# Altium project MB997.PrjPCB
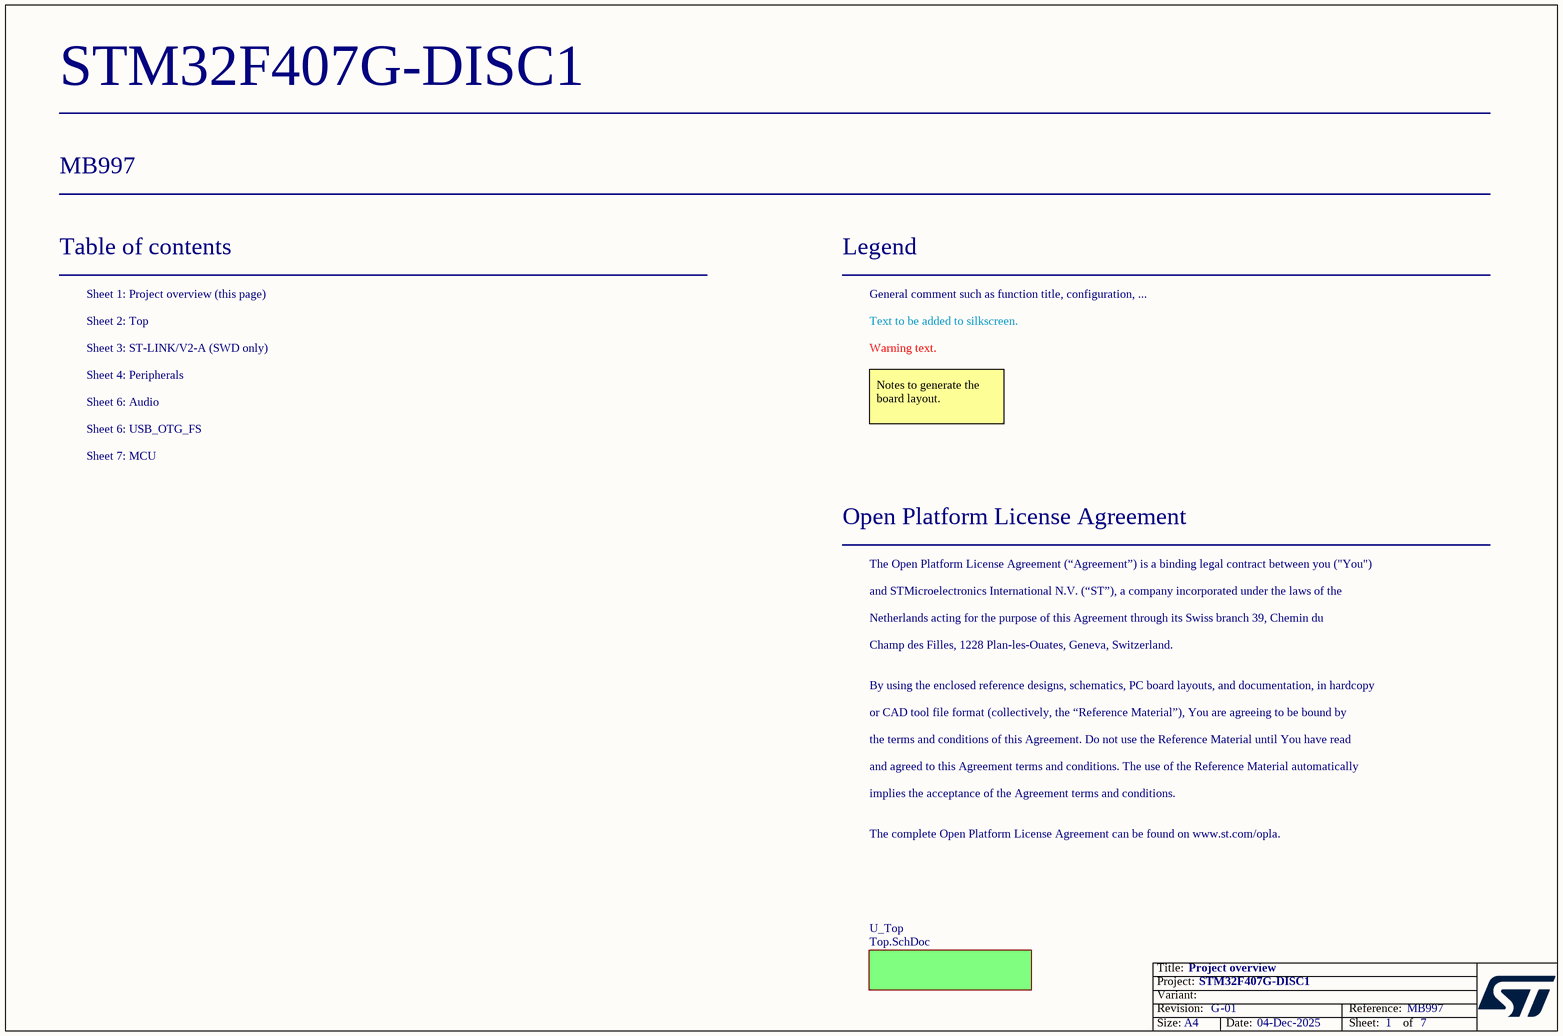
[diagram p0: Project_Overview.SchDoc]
Board_reference: MB997; Board_PCB_REVISION: G; Board_name: STM32F407G-DISC1; Board_Document_Date: 04-Dec-2025; Board_assembly_revision: 01
7 sheets, 207 parts. Net scope: flat (ports and power ports of the same name join across sheets).
Board file: MB997.PcbDoc
Sheets:
  Project_Overview.SchDoc
    U_Top = Top.SchDoc
      U_ST_LINK = ST_LINK_V2.SCHDOC
      U_STM32Fx = STM32Fx.SchDoc
      U_USB_OTG_FS = USB_OTG_FS.SchDoc
      U_Audio = Audio.SchDoc
      U_IO_Peripherals = IO_Peripherals.SchDoc

## Sheet Project_Overview.SchDoc: Project overview
size A4; Date: Not used; ApprovedBy: Not used; CheckedBy: Not used; Author: Not used; CompanyName: STMicroelectronics; DrawnBy: Not used; Engineer: Not used; Organization: Not used; Address1: Not used; Address2: Not used; Address3: Not used; Address4: Not used; DocumentNumber: 1; Revision: Not used; SheetNumber: 1; SheetTotal: 7

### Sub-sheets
U_Top = Top.SchDoc: no entries

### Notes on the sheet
- Table of contents
- Sheet 1: Project overview (this page)
- Legend
- General comment such as function title, configuration, ...
- Sheet 2: Top
- Sheet 3: ST-LINK/V2-A (SWD only)
- Sheet 4: Peripherals
- Text to be added to silkscreen.
- Warning text.
- Sheet 6: Audio
- Sheet 6: USB_OTG_FS
- Notes to generate the board layout.
- Sheet 7: MCU
- Open Platform License Agreement
- The Open Platform License Agreement (“Agreement”) is a binding legal contract between you ("You")
- and STMicroelectronics International N.V. (“ST”), a company incorporated under the laws of the
- Netherlands acting for the purpose of this Agreement through its Swiss branch 39, Chemin du
- Champ des Filles, 1228 Plan-les-Ouates, Geneva, Switzerland.
- By using the enclosed reference designs, schematics, PC board layouts, and documentation, in hardcopy
- or CAD tool file format (collectively, the “Reference Material”), You are agreeing to be bound by
- the terms and conditions of this Agreement. Do not use the Reference Material until You have read
- and agreed to this Agreement terms and conditions. The use of the Reference Material automatically
- implies the acceptance of the Agreement terms and conditions.
- The complete Open Platform License Agreement can be found on www.st.com/opla.

## Sheet Top.SchDoc: TOP
size A4; DocumentNumber: 2; Revision: D.1(PCB.SCH); SheetNumber: 2; SheetTotal: 7
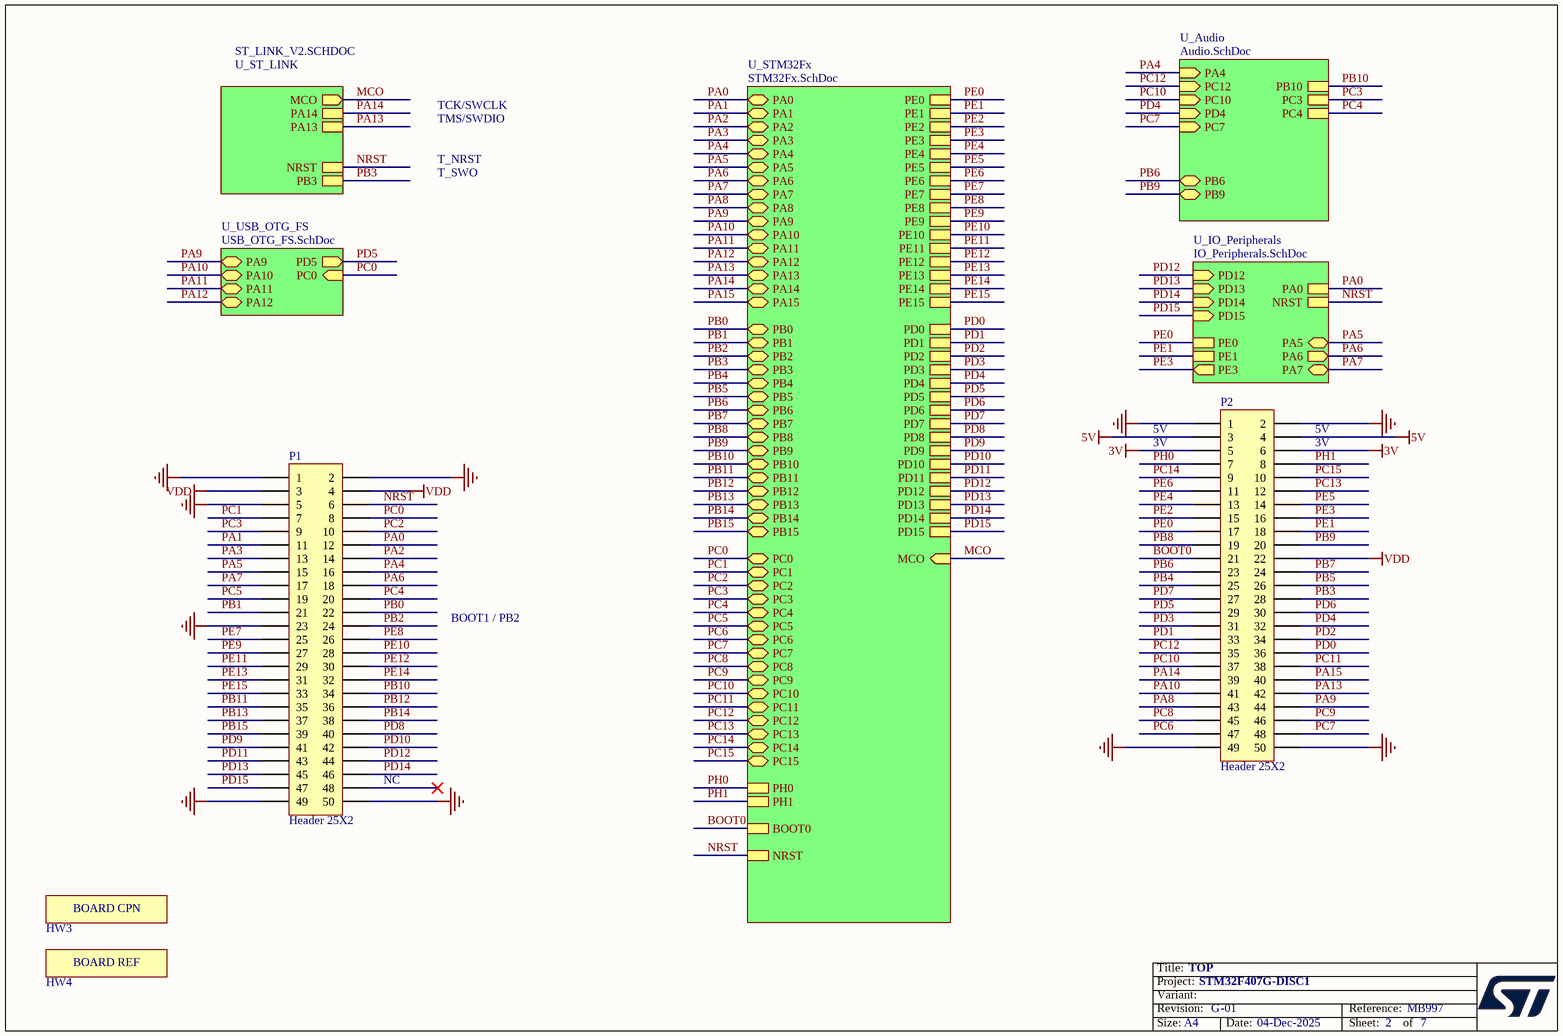
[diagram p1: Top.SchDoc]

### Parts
HW3  STICKER_BOARD_CPN  [STICKER_25X9_]  (value not drawn)  (no BOM)
HW4  STICKER_BOARD_REF  [STICKER_25X9_]  (value not drawn)  (no BOM)
P1  Header 25X2  [HEAD25X2$2F$2.54]
P2  Header 25X2  [HEAD25X2$2F$2.54]

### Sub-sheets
U_Audio = Audio.SchDoc: PA4 (in), PC12 (in), PC10 (in), PB6 (bidir), PB9 (bidir), PD4 (in), PC7 (in), PC3, PB10, PC4
U_IO_Peripherals = IO_Peripherals.SchDoc: PD12 (in), PA0, NRST, PD13 (in), PD14 (in), PD15 (in), PE3 (out), PA6 (out), PA7 (bidir), PA5 (bidir), PE0, PE1
U_ST_LINK = ST_LINK_V2.SCHDOC: PA13, PA14, NRST, PB3, MCO (out)
U_STM32Fx = STM32Fx.SchDoc: PA13 (bidir), PA14 (bidir), PA15 (bidir), PA12 (bidir), PA0 (bidir), PA1 (bidir), PA2 (bidir), PA3 (bidir), PA4 (bidir), PA5 (bidir), PA6 (bidir), PA7 (bidir), PA8 (bidir), PA9 (bidir), PA10 (bidir), PA11 (bidir), PB12 (bidir), PB0 (bidir), PB1 (bidir), PB2 (bidir), PB3 (bidir), PB4 (bidir), PB5 (bidir), PB6 (bidir), PB7 (bidir), PB8 (bidir), PB9 (bidir), PB10 (bidir), PB11 (bidir), PB13 (bidir), PB14 (bidir), PB15 (bidir), PC3 (bidir), PC15 (bidir), PC14 (bidir), PC13 (bidir), PC12 (bidir), PC11 (bidir), PC10 (bidir), PC9 (bidir), PC8 (bidir), PC7 (bidir), PC6 (bidir), PC5 (bidir), PC4 (bidir), PC2 (bidir), PC1 (bidir), PC0 (bidir), PD2, BOOT0, PH1, PH0, NRST, MCO (in), PE0, PE1, PE2, PE3, PE4, PE5, PE6, PE7, PE8, PE9, PE10, PE11, PE12, PE13, PE14, PE15, PD0, PD1, PD3, PD4, PD5, PD6, PD7, PD8, PD9, PD10, PD11, PD12, PD13, PD14, PD15
U_USB_OTG_FS = USB_OTG_FS.SchDoc: PD5 (out), PA11 (bidir), PA12 (bidir), PC0 (in), PA10 (bidir), PA9 (bidir)

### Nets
3V: P2.5 P2.6
5V: P2.3 P2.4
GND: P1.1 P1.2 P1.5 P1.23 P1.49 P1.50 P2.1 P2.2 P2.49 P2.50
VDD: P1.3 P1.4 P2.22
BOOT0: P2.21 ; sheet U_STM32Fx/BOOT0
MCO: sheet U_ST_LINK/MCO, sheet U_STM32Fx/MCO
NRST: P1.6 ; sheet U_ST_LINK/NRST, sheet U_STM32Fx/NRST, sheet U_IO_Peripherals/NRST
PA0: P1.12 ; sheet U_STM32Fx/PA0, sheet U_IO_Peripherals/PA0
PA1: P1.11 ; sheet U_STM32Fx/PA1
PA2: P1.14 ; sheet U_STM32Fx/PA2
PA3: P1.13 ; sheet U_STM32Fx/PA3
PA4: P1.16 ; sheet U_STM32Fx/PA4, sheet U_Audio/PA4
PA5: P1.15 ; sheet U_STM32Fx/PA5, sheet U_IO_Peripherals/PA5
PA6: P1.18 ; sheet U_STM32Fx/PA6, sheet U_IO_Peripherals/PA6
PA7: P1.17 ; sheet U_STM32Fx/PA7, sheet U_IO_Peripherals/PA7
PA8: P2.43 ; sheet U_STM32Fx/PA8
PA9: P2.44 ; sheet U_STM32Fx/PA9, sheet U_USB_OTG_FS/PA9
PA10: P2.41 ; sheet U_STM32Fx/PA10, sheet U_USB_OTG_FS/PA10
PA11: sheet U_STM32Fx/PA11, sheet U_USB_OTG_FS/PA11
PA12: sheet U_STM32Fx/PA12, sheet U_USB_OTG_FS/PA12
PA13: P2.42 ; sheet U_ST_LINK/PA13, sheet U_STM32Fx/PA13
PA14: P2.39 ; sheet U_ST_LINK/PA14, sheet U_STM32Fx/PA14
PA15: P2.40 ; sheet U_STM32Fx/PA15
PB0: P1.22 ; sheet U_STM32Fx/PB0
PB1: P1.21 ; sheet U_STM32Fx/PB1
PB2: P1.24 ; sheet U_STM32Fx/PB2
PB3: P2.28 ; sheet U_ST_LINK/PB3, sheet U_STM32Fx/PB3
PB4: P2.25 ; sheet U_STM32Fx/PB4
PB5: P2.26 ; sheet U_STM32Fx/PB5
PB6: P2.23 ; sheet U_STM32Fx/PB6, sheet U_Audio/PB6
PB7: P2.24 ; sheet U_STM32Fx/PB7
PB8: P2.19 ; sheet U_STM32Fx/PB8
PB9: P2.20 ; sheet U_STM32Fx/PB9, sheet U_Audio/PB9
PB10: P1.34 ; sheet U_STM32Fx/PB10, sheet U_Audio/PB10
PB11: P1.35 ; sheet U_STM32Fx/PB11
PB12: P1.36 ; sheet U_STM32Fx/PB12
PB13: P1.37 ; sheet U_STM32Fx/PB13
PB14: P1.38 ; sheet U_STM32Fx/PB14
PB15: P1.39 ; sheet U_STM32Fx/PB15
PC0: P1.8 ; sheet U_STM32Fx/PC0, sheet U_USB_OTG_FS/PC0
PC1: P1.7 ; sheet U_STM32Fx/PC1
PC2: P1.10 ; sheet U_STM32Fx/PC2
PC3: P1.9 ; sheet U_STM32Fx/PC3, sheet U_Audio/PC3
PC4: P1.20 ; sheet U_STM32Fx/PC4, sheet U_Audio/PC4
PC5: P1.19 ; sheet U_STM32Fx/PC5
PC6: P2.47 ; sheet U_STM32Fx/PC6
PC7: P2.48 ; sheet U_STM32Fx/PC7, sheet U_Audio/PC7
PC8: P2.45 ; sheet U_STM32Fx/PC8
PC9: P2.46 ; sheet U_STM32Fx/PC9
PC10: P2.37 ; sheet U_STM32Fx/PC10, sheet U_Audio/PC10
PC11: P2.38 ; sheet U_STM32Fx/PC11
PC12: P2.35 ; sheet U_STM32Fx/PC12, sheet U_Audio/PC12
PC13: P2.12 ; sheet U_STM32Fx/PC13
PC14: P2.9 ; sheet U_STM32Fx/PC14
PC15: P2.10 ; sheet U_STM32Fx/PC15
PD0: P2.36 ; sheet U_STM32Fx/PD0
PD1: P2.33 ; sheet U_STM32Fx/PD1
PD2: P2.34 ; sheet U_STM32Fx/PD2
PD3: P2.31 ; sheet U_STM32Fx/PD3
PD4: P2.32 ; sheet U_STM32Fx/PD4, sheet U_Audio/PD4
PD5: P2.29 ; sheet U_STM32Fx/PD5, sheet U_USB_OTG_FS/PD5
PD6: P2.30 ; sheet U_STM32Fx/PD6
PD7: P2.27 ; sheet U_STM32Fx/PD7
PD8: P1.40 ; sheet U_STM32Fx/PD8
PD9: P1.41 ; sheet U_STM32Fx/PD9
PD10: P1.42 ; sheet U_STM32Fx/PD10
PD11: P1.43 ; sheet U_STM32Fx/PD11
PD12: P1.44 ; sheet U_STM32Fx/PD12, sheet U_IO_Peripherals/PD12
PD13: P1.45 ; sheet U_STM32Fx/PD13, sheet U_IO_Peripherals/PD13
PD14: P1.46 ; sheet U_STM32Fx/PD14, sheet U_IO_Peripherals/PD14
PD15: P1.47 ; sheet U_STM32Fx/PD15, sheet U_IO_Peripherals/PD15
PE0: P2.17 ; sheet U_STM32Fx/PE0, sheet U_IO_Peripherals/PE0
PE1: P2.18 ; sheet U_STM32Fx/PE1, sheet U_IO_Peripherals/PE1
PE2: P2.15 ; sheet U_STM32Fx/PE2
PE3: P2.16 ; sheet U_STM32Fx/PE3, sheet U_IO_Peripherals/PE3
PE4: P2.13 ; sheet U_STM32Fx/PE4
PE5: P2.14 ; sheet U_STM32Fx/PE5
PE6: P2.11 ; sheet U_STM32Fx/PE6
PE7: P1.25 ; sheet U_STM32Fx/PE7
PE8: P1.26 ; sheet U_STM32Fx/PE8
PE9: P1.27 ; sheet U_STM32Fx/PE9
PE10: P1.28 ; sheet U_STM32Fx/PE10
PE11: P1.29 ; sheet U_STM32Fx/PE11
PE12: P1.30 ; sheet U_STM32Fx/PE12
PE13: P1.31 ; sheet U_STM32Fx/PE13
PE14: P1.32 ; sheet U_STM32Fx/PE14
PE15: P1.33 ; sheet U_STM32Fx/PE15
PH0: P2.7 ; sheet U_STM32Fx/PH0
PH1: P2.8 ; sheet U_STM32Fx/PH1

Not connected (* = marked no-connect by the designer): P1 48*

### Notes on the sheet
- TCK/SWCLK
- TMS/SWDIO
- T_SWO
- T_NRST
- 5V
- 3V
- (near P2) 5V
- (near P2) 3V
- BOOT1 / PB2
- (near P1) NC

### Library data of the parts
P1 = Header 25X2: Header, 25-Pin, Dual row; Manuf_Part_1: 313250S141145; Manuf_1: LYCN
P2 = Header 25X2: Header, 25-Pin, Dual row; Manuf_1: LYCN; Manuf_Part_1: 313250S141145

## Sheet ST_LINK_V2.SCHDOC: ST-LINK/V2-A (SWD only)
size A4; DocumentNumber: 3; Revision: D.1(PCB.SCH); SheetNumber: 3; SheetTotal: 7
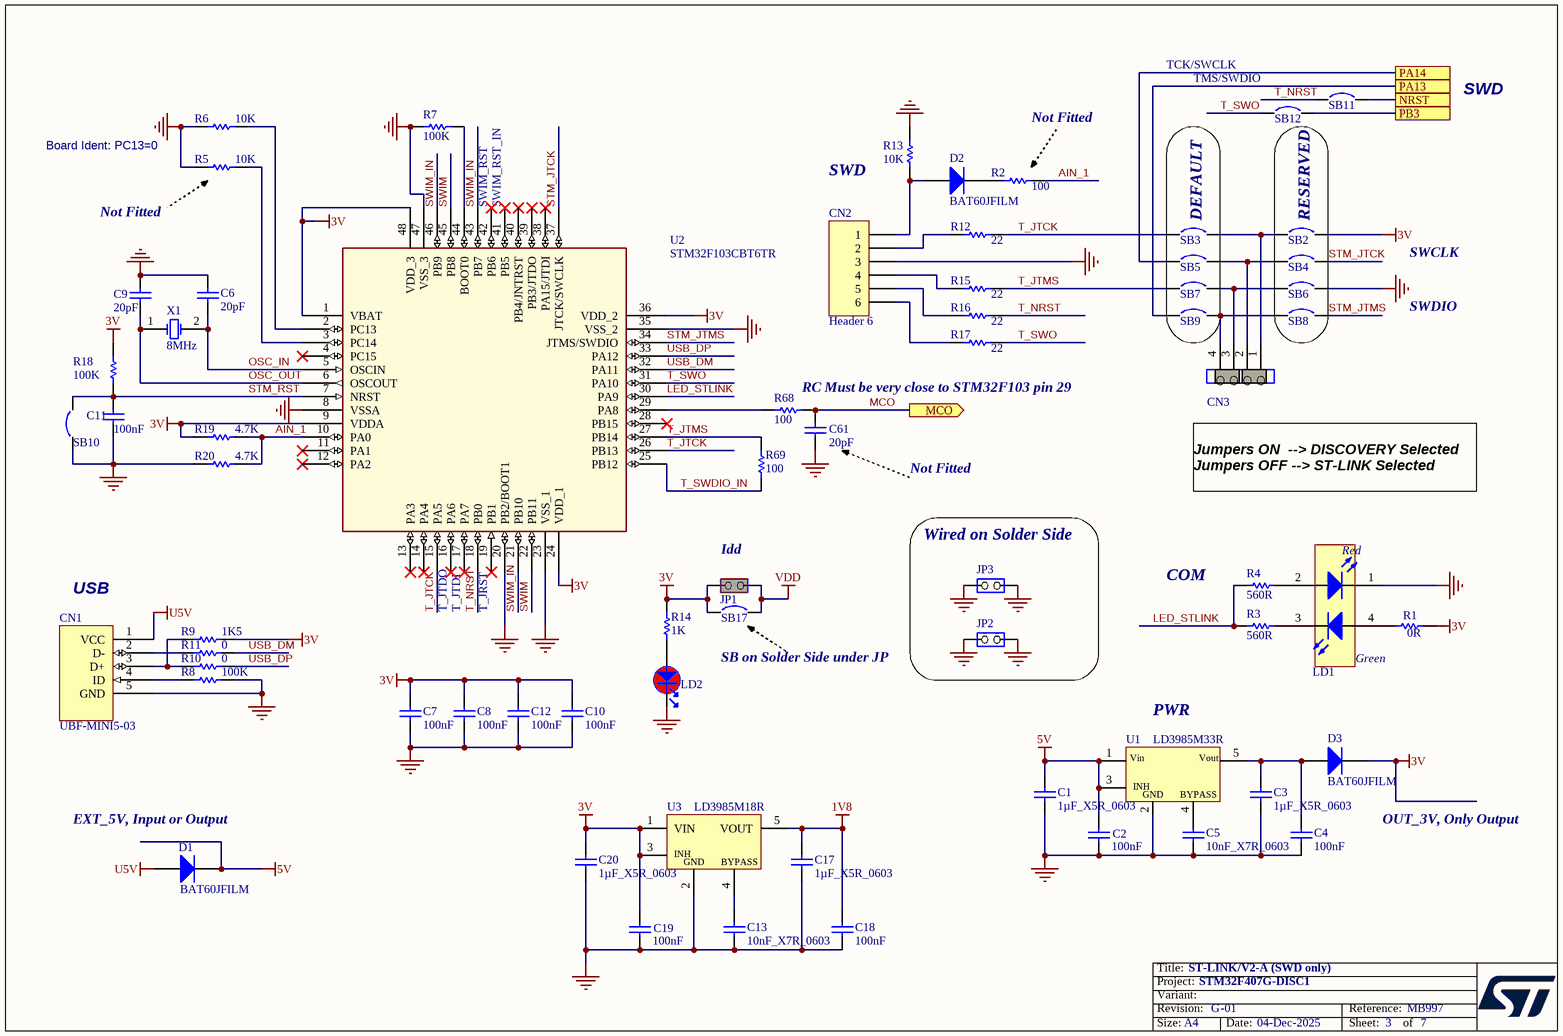
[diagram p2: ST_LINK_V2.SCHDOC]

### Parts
C1  1µF_X5R_0603  [0603C]
C2  100nF  [0402C]
C3  1µF_X5R_0603  [0603C]
C4  100nF  [0402C]
C5  10nF_X7R_0603  [0603C]
C6  20pF  [0402C]
C7  100nF  [0402C]
C8  100nF  [0402C]
C9  20pF  [0402C]
C10  100nF  [0402C]
C11  100nF  [0402C]
C12  100nF  [0402C]
C13  10nF_X7R_0603  [0603C]
C17  1µF_X5R_0603  [0603C]
C18  100nF  [0402C]
C19  100nF  [0402C]
C20  1µF_X5R_0603  [0603C]
C61  20pF  [0603C]
CN1  UBF-MINI5-03  [USB-MINI-B-SMD-A_]
CN2  Header 6  [HEADER6$2F$2.54]
CN3  Jumper_Header 4x1 fitted 1-2_3-4  [CON_SAMTEC_TSW-104-07-G-S]  (value not drawn)
D1  BAT60JFILM  [SOD323$2F$A]
D2  BAT60JFILM  [SOD323$2F$A]
D3  BAT60JFILM  [SOD323$2F$A]
JP1  Jumper_Header 2x1 Fitted  [CON_SAMTEC_TSW-102-07-G-S]  (value not drawn)
JP2  (no value)  [SIP2$2F$2.54]
JP3  (no value)  [SIP2$2F$2.54]
LD1  LD_BICOLOR_CMS_1  [LED_BI-GR_HSMF-A201-A00J1]  (value not drawn)
LD2  LED_red  [LED_0603_RED]  (value not drawn)
R1  0R  [0603R]
R2  100  [0402R]
R3  560R  [0402R]
R4  560R  [0402R]
R5  10K  [0402R]
R6  10K  [0402R]
R7  100K  [0402R]
R8  100K  [0402R]
R9  1K5  [0402R]
R10  0  [0603R]
R11  0  [0603R]
R12  22  [0402R]
R13  10K  [0402R]
R14  1K  [0402R]
R15  22  [0402R]
R16  22  [0402R]
R17  22  [0402R]
R18  100K  [0402R]
R19  4.7K  [0402R]
R20  4.7K  [0402R]
R68  100  [0603R]
R69  100  [0402R]
SB2  Circuit Breaker  [JUMPER]  (value not drawn)
SB3  Circuit Breaker  [JUMPER]  (value not drawn)
SB4  Circuit Breaker  [JUMPER]  (value not drawn)
SB5  Circuit Breaker  [JUMPER]  (value not drawn)
SB6  Circuit Breaker  [JUMPER]  (value not drawn)
SB7  Circuit Breaker  [JUMPER]  (value not drawn)
SB8  Circuit Breaker  [JUMPER]  (value not drawn)
SB9  Circuit Breaker  [JUMPER]  (value not drawn)
SB10  Circuit Breaker  [JUMPER]  (value not drawn)
SB11  Circuit Breaker  [JUMPER]  (value not drawn)
SB12  Circuit Breaker  [JUMPER]  (value not drawn)
SB17  Circuit Breaker  [JUMPER]  (value not drawn)
U1  LD3985M33R  [SOT-23-5L]
U2  STM32F103CBT6TR  [LQFP48$2F$0.5MM$5C$9X9B]
U3  LD3985M18R  [REG_SOT23-5L]
X1  8MHz  [HC-49A]

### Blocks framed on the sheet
DEFAULT: SB3 SB5 SB7 SB9
RESERVED: SB2 SB4 SB6 SB8
Wired on Solder Side: JP2 JP3

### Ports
MCO (out), NRST, PA13, PA14, PB3

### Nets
1V8: C17.1 C18.2 U3.5(VOUT)
3V: C7.2 C8.2 C10.2 C12.1 C19.2 C20.2 D3.2(K) JP1.1(COMMON) R1.2 R9.2 R14.2 R18.2 R19.1 SB2.2 SB17.1 U2.1(VBAT) U2.9(VDDA) U2.24(VDD_1) U2.36(VDD_2) U2.48(VDD_3) U3.1(VIN) U3.3(CE)
5V: C1.2 C2.2 D1.2(K) U1.1(Vin) U1.3(CE)
GND: C1.1 C2.1 C3.2 C4.1 C5.1 C6.1 C7.1 C8.1 C9.1 C10.1 C11.1 C12.2 C13.1 C17.2 C18.1 C19.1 C20.1 C61.2 CN1.5(GND) CN2.3 JP2.1(COMMON) JP2.2(NO) JP3.1(COMMON) JP3.2(NO) LD1.1(RED_cathode) LD2.2 R5.1 R6.1 R7.1 R8.2 R13.2 R20.1 SB6.2 SB10.1 U1.2(GND) U2.8(VSSA) U2.20(PB2/BOOT1) U2.23(VSS_1) U2.35(VSS_2) U2.47(VSS_3) U3.2(GND)
U5V: CN1.1(VCC) D1.1(A)
VDD: JP1.2(NO) SB17.2
AIN_1: R2.2 R19.2 R20.2 U2.10(PA0)
LED_STLINK: R3.1 R4.1 U2.30(PA9)
MCO: C61.1 R68.2 ; port MCO
NRST: SB11.2 ; port NRST
OSC_IN: C6.2 U2.5(OSCIN) X1.2(OSC2)
OSC_OUT: C9.2 U2.6(OSCOUT) X1.1(OSC1)
PA13: SB9.1 ; port PA13
PA14: SB5.1 ; port PA14
PB3: SB12.2 ; port PB3
STM_JTCK: SB4.2 U2.37(JTCK/SWCLK)
STM_JTMS: SB8.2 U2.34(JTMS/SWDIO)
STM_RST: C11.2 R18.1 SB10.2 U2.7(NRST)
SWIM: U2.22(PB11) U2.45(PB8)
SWIM_IN: U2.21(PB10) U2.43(PB7) U2.46(PB9)
T_JTCK: R12.2 SB3.1 U2.15(PA5) U2.26(PB13)
T_JTMS: R15.2 R69.2 SB7.1 U2.27(PB14)
T_NRST: R16.2 SB11.1 U2.18(PB0)
T_SWDIO_IN: R69.1 U2.25(PB12)
T_SWO: R17.2 SB12.1 U2.31(PA10)
USB_DM: R11.2 U2.32(PA11)
USB_DP: R10.2 U2.33(PA12)
NetC3_1: C3.1 C4.2 D3.1(A) U1.5(Vout)
NetC5_2: C5.2 U1.4(BYPASS)
NetC13_2: C13.2 U3.4(BYPASS)
NetCN1_2: CN1.2(D-) R11.1
NetCN1_3: CN1.3(D+) R9.1 R10.1
NetCN1_4: CN1.4(ID) R8.1
NetCN2_1: CN2.1 D2.1(A) R13.1
NetCN2_2: CN2.2 R12.1
NetCN2_4: CN2.4 R15.1
NetCN2_5: CN2.5 R16.1
NetCN2_6: CN2.6 R17.1
NetCN3_1: CN3.1 SB2.1 SB3.2
NetCN3_2: CN3.2 SB4.1 SB5.2
NetCN3_3: CN3.3 SB6.1 SB7.2
NetCN3_4: CN3.4 SB8.1 SB9.2
NetD2_2: D2.2(K) R2.1
NetLD1_2: LD1.2(Red_anode) R4.2
NetLD1_3: LD1.3(YellowGreen_cathode) R3.2
NetLD1_4: LD1.4(YellowGreen_anode) R1.1
NetLD2_1: LD2.1 R14.1
NetR5_2: R5.2 U2.3(PC14)
NetR6_2: R6.2 U2.2(PC13)
NetR7_2: R7.2 U2.44(BOOT0)
NetR68_1: R68.1 U2.29(PA8)

Not connected (* = marked no-connect by the designer): U2 4(PC15)* 11(PA1)* 12(PA2)* 13(PA3)* 14(PA4)* 16(PA6)* 17(PA7)* 19(PB1)* 28(PB15)* 38(PA15/JTDI)* 39(PB3/JTDO)* 40(PB4/JNTRST)* 41(PB5)* 42(PB6)*

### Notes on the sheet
- TCK/SWCLK
- (near SB12) TMS/SWDIO
- SWD
- Board Ident: PC13=0
- Not Fitted
- SWIM_RST
- SWIM_RST_IN
- SWCLK
- SWDIO
- (near R68) RC Must be very close to STM32F103 pin 29
- Jumpers ON  --> DISCOVERY Selected
  Jumpers OFF --> ST-LINK Selected
- (near JP1) Idd
- COM
- (near CN1) USB
- (near U2) T_JTDO
- (near U2) T_JTDI
- (near U2) T_JRST
- SB on Solder Side under JP
- (near U1) PWR
- (near D1) EXT_5V, Input or Output
- OUT_3V, Only Output

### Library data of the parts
C1 C3 C17 C20 = CAP SMD 0603  X5R 1µF 25V 10%: 0603  X5R 1µF; Manuf_1: YAGEO; Manuf_Part_1: CC0603KRX5R7BB105; Value: 1uF; Rated voltage: 25V; Tolerance: 10%
C2 C4 C7 C8 C10-C12 C18 C19 = Cap: Capacitor; Manuf_Part_1: CC0402KRX7R7BB104; Manuf_1: YAGEO
C5 C13 = CAP SMD 0603  X7R 10000PF 50V 10%: 0603  X7R 10NF; Manuf_1: YAGEO; Manuf_Part_1: CC0603KRX7R9BB103; Order code RS: 2040779; Rated voltage: 50V; Tolerance: 10%
C6 C9 = Cap: Capacitor; Manuf_Part_1: CC0402JRNPO9BN200; Manuf_1: YAGEO
C61 = Cap: Capacitor; Fitted: NO
CN1 = USB-MINI-typeB connector_: Manuf_1: MTCONN
CN2 = Header 6: Header, 6-Pin; Manuf_Part_1: 313106S141116; Manuf_1: LYCN
D1-D3 = BAT60JFILM: Manuf_1: STM; Code - JEDEC: DO-214-AB; Provided: ST
JP2 JP3 = JP2: Manuf_1: LYCN; Manuf_Part_1: 313102S141145
R1 = res1: Resistor; Manuf_Part_1: RC0603JR-070RL; Manuf_1: YAGEO; Value: 0
R2 = res1: Resistor; Fitted: NO
R3 R4 = res1: Resistor, 560R, 0402, +/-1%, 1/16W; Manuf_Part_1: RC0402FR-07560RL; Manuf_1: YAGEO; Value: 560
R5 = res1: Resistor; Manuf_Part_1: RC0402FR-0710KL; Manuf_1: YAGEO; Fitted: NO
R6 R13 = res1: Resistor; Manuf_Part_1: RC0402FR-0710KL; Manuf_1: YAGEO
R7 R8 R18 = res1: Resistor; Manuf_Part_1: RC0402FR-07100KL; Manuf_1: YAGEO
R9 = res1: Resistor; Manuf_Part_1: RC0402FR-071K5L; Manuf_1: YAGEO
R10 R11 = res1: Resistor; Manuf_Part_1: RC0603JR-070RL; Manuf_1: YAGEO
R12 R15-R17 = res1: Resistor; Manuf_Part_1: RC0402FR-0722RL; Manuf_1: YAGEO
R14 = res1: Resistor; Manuf_Part_1: RC0402FR-071KL; Manuf_1: YAGEO
R19 R20 = res1: Resistor; Manuf_Part_1: RC0402FR-074K7L; Manuf_1: YAGEO
R68 = res1: Resistor; Manuf_Part_1: RC0603FR-07100RL; Manuf_1: YAGEO
R69 = res1: Resistor; Manuf_Part_1: RC0402FR-07100RL; Manuf_1: YAGEO
SB2 SB4 SB6 SB8 SB10 SB17 = Circuit Breaker: Solder: NO
SB3 SB5 SB7 SB9 SB11 SB12 = Circuit Breaker: Solder: YES
U1 = LD3985M33R: Ultra low drop-low noise BiCMOS voltage, regulators low ESR capacitors compatible; Manuf_1: STM; Provided: ST
U2 = STM32F103CBT6: Medium-density performance line ARM-based 32-bit MCU with 128KB Flash; Manuf_1: STM; Ref St: xxxxxxxx; Provided: ST; ECCN_US/EU: 3A991A2/NEC
X1 = XTAL: Crystal Oscillator; Manuf_Part_1: HC-49S-C20QSA-8.000MHZ; Manuf_1: jfvny

## Sheet STM32Fx.SchDoc: MCU
size A4; DocumentNumber: 7; Revision: D.1(PCB.SCH); SheetNumber: 7; SheetTotal: 7
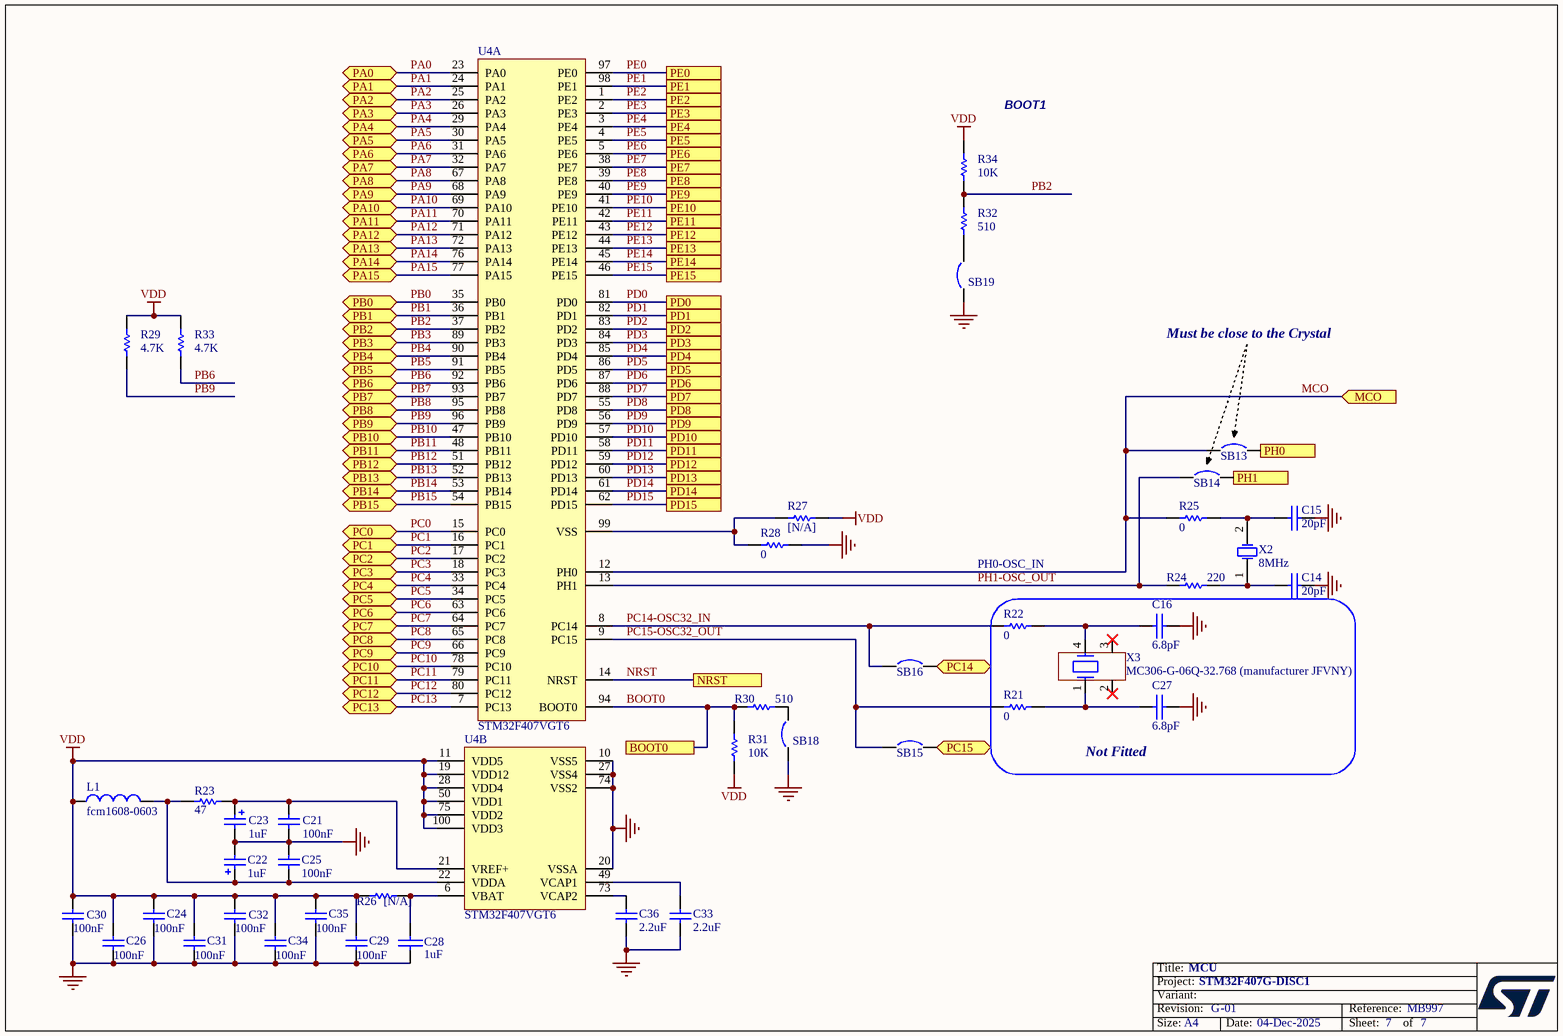
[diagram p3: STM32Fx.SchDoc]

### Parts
C14  20pF  [0603C]
C15  20pF  [0603C]
C16  6.8pF  [0603C]
C21  100nF  [0402C]
C22  1uF  [CASE-A]
C23  1uF  [CASE-A]
C24  100nF  [0402C]
C25  100nF  [0402C]
C26  100nF  [0402C]
C27  6.8pF  [0603C]
C28  1uF  [0603C]
C29  100nF  [0402C]
C30  100nF  [0402C]
C31  100nF  [0402C]
C32  100nF  [0402C]
C33  2.2uF  [CASE-A]
C34  100nF  [0402C]
C35  100nF  [0402C]
C36  2.2uF  [CASE-A]
L1  fcm1608-0603  [0603L]
R21  0  [0603R]
R22  0  [0603R]
R23  47  [0603R]
R24  220  [0603R]
R25  0  [0603R]
R26  [N/A]  [0603R]
R27  [N/A]  [0603R]
R28  0  [0603R]
R29  4.7K  [0402R]
R30  510  [0603R]
R31  10K  [0402R]
R32  510  [0603R]
R33  4.7K  [0402R]
R34  10K  [0402R]
SB13  Circuit Breaker  [JUMPER]  (value not drawn)
SB14  Circuit Breaker  [JUMPER]  (value not drawn)
SB15  Circuit Breaker  [JUMPER]  (value not drawn)
SB16  Circuit Breaker  [JUMPER]  (value not drawn)
SB18  Circuit Breaker  [JUMPER]  (value not drawn)
SB19  Circuit Breaker  [JUMPER]  (value not drawn)
U4  STM32F407VGT6  [QFP100-1414]  (parts A,B of 2)
X2  8MHz  [HC-49A]
X3  MC306-G-06Q-32.768 (manufacturer JFVNY)  [MC306-CRYSTAL]

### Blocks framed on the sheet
Not Fitted: C16 C27 R21 R22 X3

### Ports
BOOT0, MCO (in), NRST, PA0 (bidir), PA1 (bidir), PA2 (bidir), PA3 (bidir), PA4 (bidir), PA5 (bidir), PA6 (bidir), PA7 (bidir), PA8 (bidir), PA9 (bidir), PA10 (bidir), PA11 (bidir), PA12 (bidir), PA13 (bidir), PA14 (bidir), PA15 (bidir), PB0 (bidir), PB1 (bidir), PB2 (bidir), PB3 (bidir), PB4 (bidir), PB5 (bidir), PB6 (bidir), PB7 (bidir), PB8 (bidir), PB9 (bidir), PB10 (bidir), PB11 (bidir), PB12 (bidir), PB13 (bidir), PB14 (bidir), PB15 (bidir), PC0 (bidir), PC1 (bidir), PC2 (bidir), PC3 (bidir), PC4 (bidir), PC5 (bidir), PC6 (bidir), PC7 (bidir), PC8 (bidir), PC9 (bidir), PC10 (bidir), PC11 (bidir), PC12 (bidir), PC13 (bidir), PC14 (bidir), PC15 (bidir), PD0, PD1, PD2, PD3, PD4, PD5, PD6, PD7, PD8, PD9, PD10, PD11, PD12, PD13, PD14, PD15, PE0, PE1, PE2, PE3, PE4, PE5, PE6, PE7, PE8, PE9, PE10, PE11, PE12, PE13, PE14, PE15, PH0, PH1

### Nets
GND: C14.1 C15.1 C16.2 C21.1 C22.2 C23.2 C24.2 C25.1 C26.1 C27.2 C28.2 C29.1 C30.1 C31.1 C32.1 C33.2 C34.1 C35.2 C36.2 R28.2 SB18.1 SB19.1 U4.10(VSS5) U4.20(VSSA) U4.27(VSS4) U4.74(VSS2)
VDD: C24.1 C26.2 C29.2 C30.2 C31.2 C32.2 C34.2 C35.1 L1.1 R26.1 R27.2 R29.1 R31.2 R33.1 R34.1 U4.11(VDD5) U4.19(VDD12) U4.28(VDD4) U4.50(VDD1) U4.75(VDD2) U4.100(VDD3)
BOOT0: R30.2 R31.1 U4.94(BOOT0) ; port BOOT0
MCO: R25.1 SB13.1 U4.12(PH0) ; port MCO
NRST: U4.14(NRST) ; port NRST
PA0: U4.23(PA0) ; port PA0
PA1: U4.24(PA1) ; port PA1
PA2: U4.25(PA2) ; port PA2
PA3: U4.26(PA3) ; port PA3
PA4: U4.29(PA4) ; port PA4
PA5: U4.30(PA5) ; port PA5
PA6: U4.31(PA6) ; port PA6
PA7: U4.32(PA7) ; port PA7
PA8: U4.67(PA8) ; port PA8
PA9: U4.68(PA9) ; port PA9
PA10: U4.69(PA10) ; port PA10
PA11: U4.70(PA11) ; port PA11
PA12: U4.71(PA12) ; port PA12
PA13: U4.72(PA13) ; port PA13
PA14: U4.76(PA14) ; port PA14
PA15: U4.77(PA15) ; port PA15
PB0: U4.35(PB0) ; port PB0
PB1: U4.36(PB1) ; port PB1
PB2: R32.1 R34.2 U4.37(PB2) ; port PB2
PB3: U4.89(PB3) ; port PB3
PB4: U4.90(PB4) ; port PB4
PB5: U4.91(PB5) ; port PB5
PB6: R33.2 U4.92(PB6) ; port PB6
PB7: U4.93(PB7) ; port PB7
PB8: U4.95(PB8) ; port PB8
PB9: R29.2 U4.96(PB9) ; port PB9
PB10: U4.47(PB10) ; port PB10
PB11: U4.48(PB11) ; port PB11
PB12: U4.51(PB12) ; port PB12
PB13: U4.52(PB13) ; port PB13
PB14: U4.53(PB14) ; port PB14
PB15: U4.54(PB15) ; port PB15
PC0: U4.15(PC0) ; port PC0
PC1: U4.16(PC1) ; port PC1
PC2: U4.17(PC2) ; port PC2
PC3: U4.18(PC3) ; port PC3
PC4: U4.33(PC4) ; port PC4
PC5: U4.34(PC5) ; port PC5
PC6: U4.63(PC6) ; port PC6
PC7: U4.64(PC7) ; port PC7
PC8: U4.65(PC8) ; port PC8
PC9: U4.66(PC9) ; port PC9
PC10: U4.78(PC10) ; port PC10
PC11: U4.79(PC11) ; port PC11
PC12: U4.80(PC12) ; port PC12
PC13: U4.7(PC13) ; port PC13
PC14: SB16.2 ; port PC14
PC14-OSC32_IN: R22.1 SB16.1 U4.8(PC14)
PC15: SB15.2 ; port PC15
PC15-OSC32_OUT: R21.1 SB15.1 U4.9(PC15)
PD0: U4.81(PD0) ; port PD0
PD1: U4.82(PD1) ; port PD1
PD2: U4.83(PD2) ; port PD2
PD3: U4.84(PD3) ; port PD3
PD4: U4.85(PD4) ; port PD4
PD5: U4.86(PD5) ; port PD5
PD6: U4.87(PD6) ; port PD6
PD7: U4.88(PD7) ; port PD7
PD8: U4.55(PD8) ; port PD8
PD9: U4.56(PD9) ; port PD9
PD10: U4.57(PD10) ; port PD10
PD11: U4.58(PD11) ; port PD11
PD12: U4.59(PD12) ; port PD12
PD13: U4.60(PD13) ; port PD13
PD14: U4.61(PD14) ; port PD14
PD15: U4.62(PD15) ; port PD15
PE0: U4.97(PE0) ; port PE0
PE1: U4.98(PE1) ; port PE1
PE2: U4.1(PE2) ; port PE2
PE3: U4.2(PE3) ; port PE3
PE4: U4.3(PE4) ; port PE4
PE5: U4.4(PE5) ; port PE5
PE6: U4.5(PE6) ; port PE6
PE7: U4.38(PE7) ; port PE7
PE8: U4.39(PE8) ; port PE8
PE9: U4.40(PE9) ; port PE9
PE10: U4.41(PE10) ; port PE10
PE11: U4.42(PE11) ; port PE11
PE12: U4.43(PE12) ; port PE12
PE13: U4.44(PE13) ; port PE13
PE14: U4.45(PE14) ; port PE14
PE15: U4.46(PE15) ; port PE15
PH0: SB13.2 ; port PH0
PH1: SB14.2 ; port PH1
PH1-OSC_OUT: R24.2 SB14.1 U4.13(PH1)
NetC14_2: C14.2 R24.1 X2.1(OSC1)
NetC15_2: C15.2 R25.2 X2.2(OSC2)
NetC16_1: C16.1 R22.2 X3.4
NetC21_2: C21.2 C23.1 R23.1 U4.21(VREF+)
NetC22_1: C22.1 C25.2 L1.2 R23.2 U4.22(VDDA)
NetC27_1: C27.1 R21.2 X3.1
NetC28_1: C28.1 R26.2 U4.6(VBAT)
NetC33_1: C33.1 U4.49(VCAP1)
NetC36_1: C36.1 U4.73(VCAP2)
NetR27_1: R27.1 R28.1 U4.99(VSS)
NetR30_1: R30.1 SB18.2
NetR32_2: R32.2 SB19.2

Not connected (* = marked no-connect by the designer): X3 2* 3*

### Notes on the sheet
- BOOT1
- Must be close to the Crystal
- PH0-OSC_IN

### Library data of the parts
C14 C15 = CAP: Capacitor; Manuf_Part_1: CC0603JRNPO9BN200; Manuf_1: YAGEO
C16 C27 = CAP: Capacitor; Fitted: NO
C21 C24-C26 C29-C32 C35 = Cap: as C2 on sheet ST_LINK_V2
C22 C23 = Cap Pol1: Polarized Capacitor (Radial); Manuf_Part_1: TAJA105K016R; Manuf_1: AVX
C28 = CAP: Capacitor; Manuf_Part_1: CC0603KRX5R7BB105; Manuf_1: YAGEO
C33 C36 = Cap Low ESR: Low ESR Ceramic Capacitor (X7R); Manuf_1: YAGEO; Order: CC1206KKX7R7BB225
C34 = Cap: Capacitor; Manuf_1: YAGEO; Manuf_Part_1: CC0402KRX7R7BB104
L1 = Inductor: Manuf_Part_1: FCM1608KF-601T03; Manuf_1: Tai-tech; Value: 100uH
R21 R22 = Res1: Resistor; Fitted: NO
R23 = Res1: Resistor; Manuf_Part_1: RC0603FR-0747RL; Manuf_1: YAGEO
R24 = Res1: Resistor; Manuf_Part_1: RC0603FR-07220RL; Manuf_1: YAGEO
R25 = Res1: Resistor; Manuf_1: YAGEO; Manuf_Part_1: RC0603JR-070RL; Fitted: NO
R26 = res1: Resistor; Manuf_Part_1: RC0603JR-070RL; Manuf_1: YAGEO; Value: 0; Fitted: NO
R27 = Res1: Resistor; Value: 0; Fitted: NO
R28 = Res1: Resistor; Manuf_Part_1: RC0603JR-070RL; Manuf_1: YAGEO
R29 R33 = res1: as R19 on sheet ST_LINK_V2
R30 = Res1: Resistor; Manuf_Part_1: RC0603FR-07510RL; Manuf_1: YAGEO
R31 = res1: as R5 on sheet ST_LINK_V2
R32 = res1: Resistor; Manuf_Part_1: RC0603FR-07510RL; Manuf_1: YAGEO
R34 = res1: as R6 on sheet ST_LINK_V2
SB13 SB14 SB19 = Circuit Breaker: Solder: NO
SB15 SB16 SB18 = Circuit Breaker: Solder: YES
U4 = STM32F407VGT6: STM32 Manta (STM32F407VGT6); Manuf_1: STM; Provided: ST; Ref St: 9175122; ECCN_US/EU: 3A991A2/NEC
X2 = XTAL: as X1 on sheet ST_LINK_V2
X3 = MC306: Fitted: NO

## Sheet USB_OTG_FS.SchDoc: USB_OTG_FS
size A4; DocumentNumber: 6; Revision: D.1(PCB.SCH); SheetNumber: 6; SheetTotal: 7
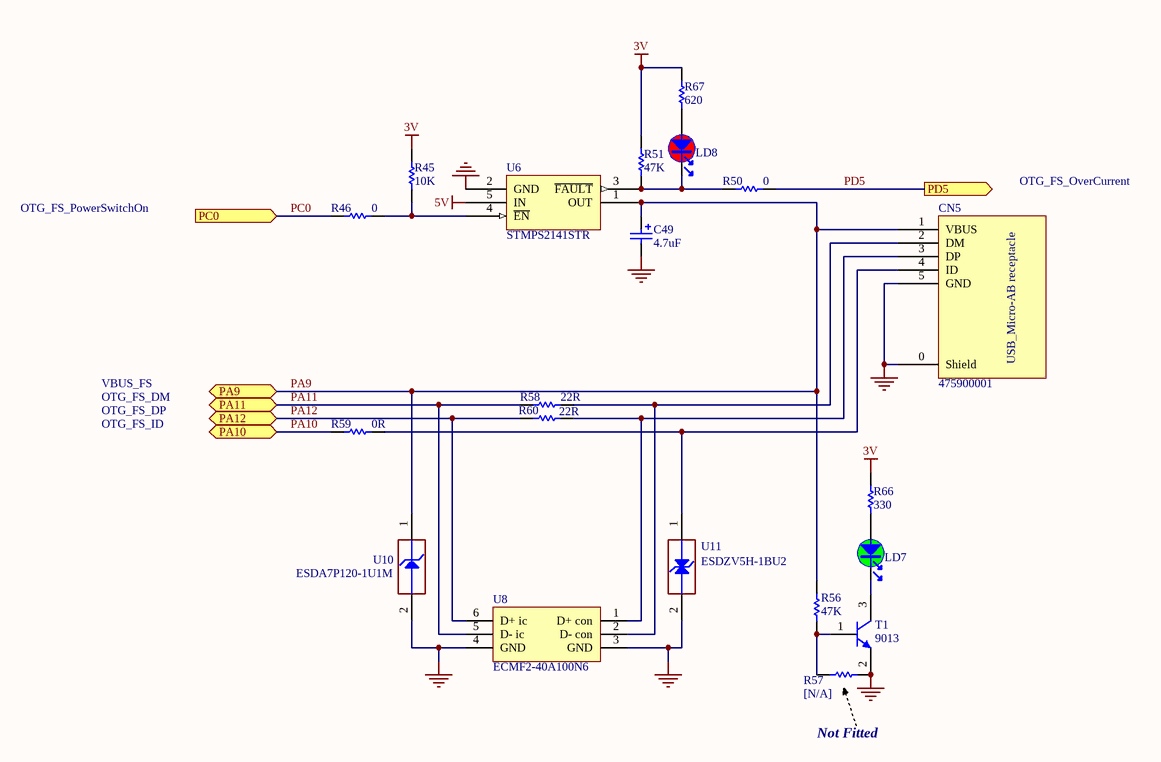
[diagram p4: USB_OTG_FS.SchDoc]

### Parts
C49  4.7uF  [CASE-A]
CN5  475900001  [USB-MICRO-AB_new]
LD7  LED_green  [LED_0603_GREEN]  (value not drawn)
LD8  LED_red  [LED_0603_RED]  (value not drawn)
R45  10K  [0402R]
R46  0  [0603R]
R50  0  [0603R]
R51  47K  [0402R]
R56  47K  [0402R]
R57  [N/A]  [0603R]
R58  22R  [0402R]
R59  0R  [0603R]
R60  22R  [0402R]
R66  330  [0603R]
R67  620  [0603R]
T1  9013  [SOT23]
U6  STMPS2141STR  [SOT-23-5L]
U8  ECMF2-40A100N6  [ESD_UQFN-6L_1P45X1P4_P040]
U10  ESDA7P120-1U1M  [ESD_QFN1610_2N_1K_2A]
U11  ESDZV5H-1BU2  [ESD-BI_ST0201_H0P24]

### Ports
PA9 (bidir), PA10 (bidir), PA11 (bidir), PA12 (bidir), PC0 (in), PD5 (out)

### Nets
3V: R45.1 R51.1 R66.2 R67.2
5V: U6.5(IN)
GND: C49.2 CN5.0(Shield) CN5.5(GND) R57.1 T1.2(E) U6.2(GND) U8.3(GND) U8.4(GND) U10.2(GND) U11.2(GND)
PA9: C49.1 CN5.1(VBUS) R56.2 U6.1(OUT) U10.1(IO1) ; port PA9
PA10: R59.2 ; port PA10
PA11: R58.1 U8.5(D-_ic) ; port PA11
PA12: R60.1 U8.6(D+_ic) ; port PA12
PC0: R46.2 ; port PC0
PD5: R50.1 ; port PD5
NetCN5_2: CN5.2(DM) R58.2 U8.2(D-_con)
NetCN5_3: CN5.3(DP) R60.2 U8.1(D+_con)
NetCN5_4: CN5.4(ID) R59.1 U11.1(IO1)
NetLD7_1: LD7.1 R66.1
NetLD7_2: LD7.2 T1.3(C)
NetLD8_1: LD8.1 R67.1
NetLD8_2: LD8.2 R50.2 R51.2 U6.3(~{FAULT})
NetR45_2: R45.2 R46.1 U6.4(~{EN})
NetR56_1: R56.1 R57.2 T1.1(B)

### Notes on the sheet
- OTG_FS_PowerSwitchOn
- OTG_FS_OverCurrent
- VBUS_FS
- OTG_FS_ID
- OTG_FS_DM
- OTG_FS_DP
- Not Fitted

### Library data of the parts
C49 = Cap Pol1: Polarized Capacitor (Radial); Manuf_Part_1: TAJA475K016R; Manuf_1: AVX
CN5 = 475900001_: Manuf_Part_1: 47590-0001; Manuf_1: Molex; Value: 47590-0001
R45 = res1: as R6 on sheet ST_LINK_V2
R46 R50 = Res1: as R28 on sheet STM32Fx
R51 R56 = res1: Resistor; Manuf_Part_1: RC0402FR-0747KL; Manuf_1: YAGEO
R57 = res1: Resistor; Value: 1K; Fitted: NO
R58 R60 = RC0402FR-0722RL: Resistor, 22R, 0402, +/-1%, 1/16W; Value: 47K
R59 = Res1: Resistor; Manuf_Part_1: RC0603JR-070RL; Manuf_1: YAGEO; Value: 0
R66 = res1: Resistor; Manuf_Part_1: RC0603FR-07330RL; Manuf_1: YAGEO
R67 = Res1: Resistor; Manuf_Part_1: RC0603FR-07620RL; Manuf_1: YAGEO
T1 = NPN_NEW: NPN Bipolar Transistor; Manuf_Part_1: MMBT9013; Manuf_1: unisonic; Code - JEDEC: TO-226-AA; Value: MMBT9013
U6 = STMPS2141STR: Enhanced single channel power switches; Manuf_1: STM; Provided: ST
U10 = ESD-TRANSIL: Diode, ESD TVS, 5V5, 1.5uA, 6V8, QFN1610
U11 = ESD-TRANSIL-BIDIR: Diode, ESD TVS, 5V5, 50nA, 10V, 0201

## Sheet Audio.SchDoc: Audio
size A4; DocumentNumber: 5; Revision: D.1(PCB.SCH); SheetNumber: 5; SheetTotal: 7
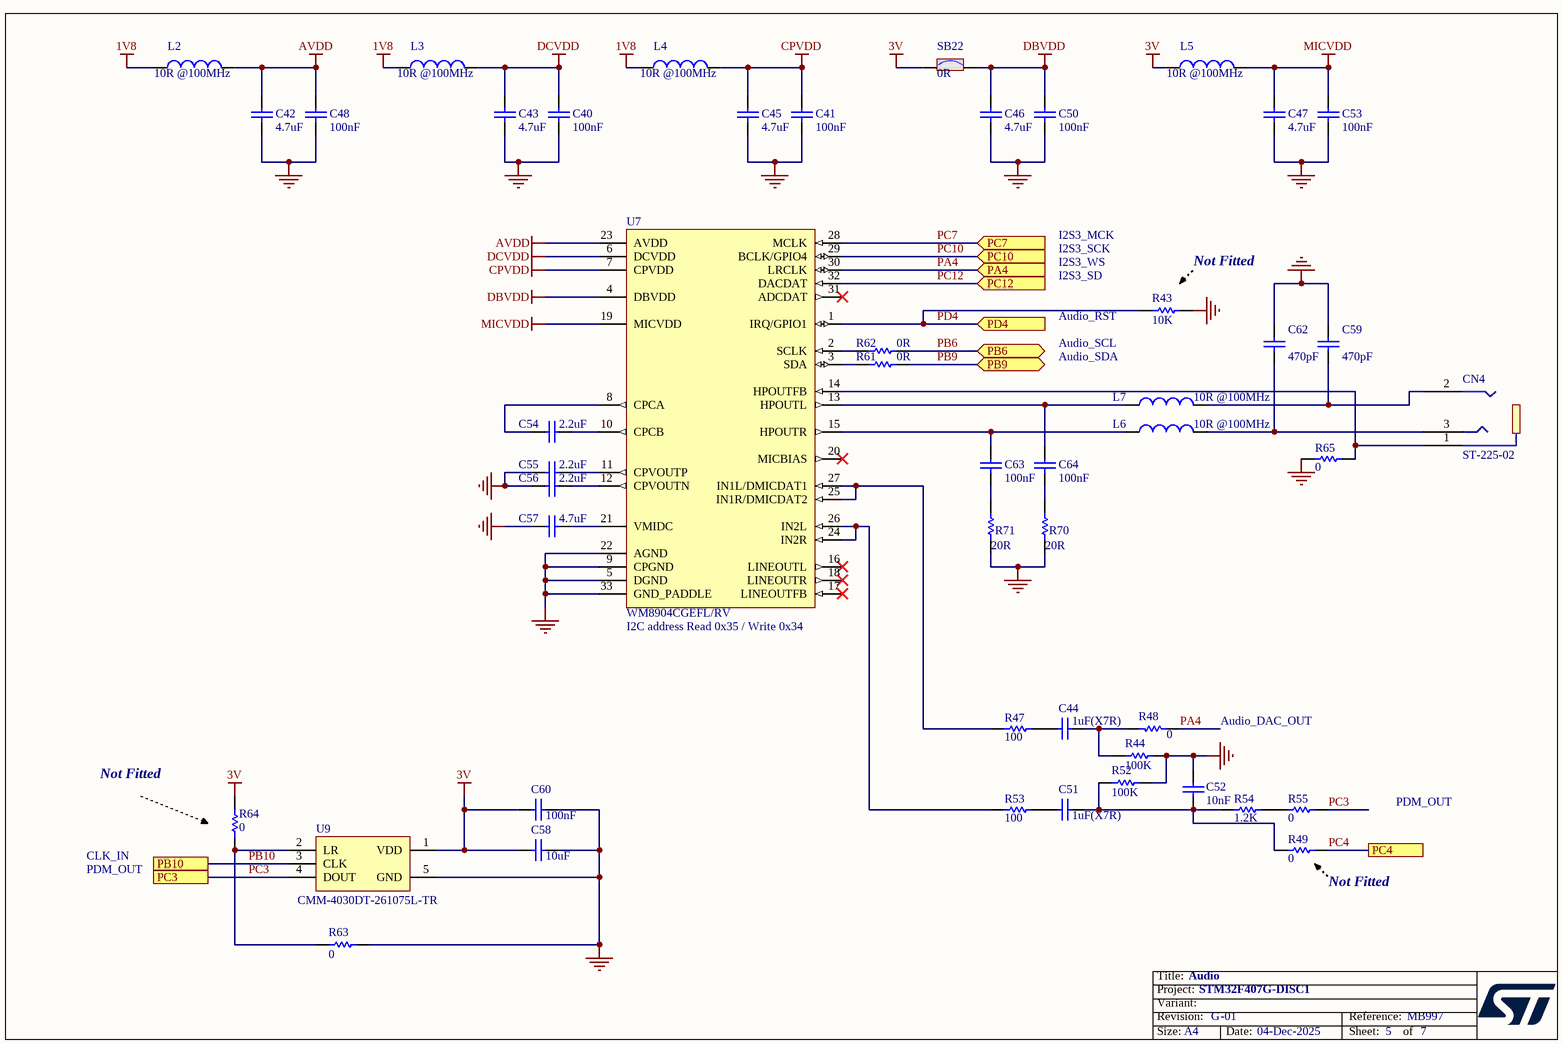
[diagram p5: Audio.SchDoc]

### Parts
C40  100nF  [C0402]
C41  100nF  [C0402]
C42  4.7uF  [C0603]
C43  4.7uF  [C0603]
C44  1uF(X7R)  [0603C]
C45  4.7uF  [C0603]
C46  4.7uF  [C0603]
C47  4.7uF  [C0603]
C48  100nF  [C0402]
C50  100nF  [C0402]
C51  1uF(X7R)  [0603C]
C52  10nF  [0603C]
C53  100nF  [C0402]
C54  2.2uF  [C0603]
C55  2.2uF  [C0603]
C56  2.2uF  [C0603]
C57  4.7uF  [C0603]
C58  10uF  [0603C]
C59  470pF  [C0402]
C60  100nF  [0402C]
C62  470pF  [C0402]
C63  100nF  [C0402]
C64  100nF  [C0402]
CN4  ST-225-02  [PCBCOMPONENT_1$2F$2_new_]
L2  10R @100MHz  [IND_0402_MURATA_BLM15H_H0P5]
L3  10R @100MHz  [IND_0402_MURATA_BLM15H_H0P5]
L4  10R @100MHz  [IND_0402_MURATA_BLM15H_H0P5]
L5  10R @100MHz  [IND_0402_MURATA_BLM15H_H0P5]
L6  10R @100MHz  [IND_0402_MURATA_BLM15H_H0P5]
L7  10R @100MHz  [IND_0402_MURATA_BLM15H_H0P5]
R43  10K  [0402R]
R44  100K  [0402R]
R47  100  [0402R]
R48  0  [0603R]
R49  0  [0603R]
R52  100K  [0402R]
R53  100  [0402R]
R54  1.2K  [0603R]
R55  0  [0603R]
R61  0R  [R0402]
R62  0R  [R0402]
R63  0  [0402R]
R64  0  [0402R]
R65  0  [0603R]
R70  20R  [R0603]
R71  20R  [R0603]
SB22  0R  [SOLDER-BRIDGE_R0603-0R]
U7  WM8904CGEFL/RV  [ICC_QFN32-EPAD_4X4_P040]
U9  CMM-4030DT-261075L-TR  [MIC_SAME-SKY_CMM-4030DT-261075-TR]

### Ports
PA4 (in), PB6 (bidir), PB9 (bidir), PB10, PC3, PC4, PC7 (in), PC10 (in), PC12 (in), PD4 (in)

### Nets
1V8: L2.1 L3.1 L4.1
3V: C58.2 C60.2 L5.1 R64.2 SB22.1 U9.1(VDD)
AVDD: C42.2 C48.2 L2.2 U7.23(AVDD)
CPVDD: C41.2 C45.2 L4.2 U7.7(CPVDD)
DBVDD: C46.2 C50.2 SB22.2 U7.4(DBVDD)
DCVDD: C40.2 C43.2 L3.2 U7.6(DCVDD)
GND: C40.1 C41.1 C42.1 C43.1 C45.1 C46.1 C47.1 C48.1 C50.1 C52.2 C53.1 C55.1 C56.1 C57.1 C58.1 C59.2 C60.1 C62.2 R43.2 R44.2 R52.2 R63.1 R65.2 R70.1 R71.1 U7.5(DGND) U7.9(CPGND) U7.22(AGND) U7.33(GND_PADDLE) U9.5(GND)
MICVDD: C47.2 C53.2 L5.2 U7.19(MICVDD)
PA4: R48.2 U7.30(LRCLK) ; port PA4
PB6: R62.2 ; port PB6
PB9: R61.2 ; port PB9
PB10: U9.3(CLK) ; port PB10
PC3: R55.1 U9.4(DOUT) ; port PC3
PC4: R49.1 ; port PC4
PC7: U7.28(MCLK) ; port PC7
PC10: U7.29(BCLK/GPIO4) ; port PC10
PC12: U7.32(DACDAT) ; port PC12
PD4: R43.1 U7.1(IRQ/GPIO1) ; port PD4
NetC44_1: C44.1 R47.1
NetC44_2: C44.2 R44.1 R48.1
NetC51_1: C51.1 R53.1
NetC51_2: C51.2 C52.1 R49.2 R52.1 R54.1
NetC54_1: C54.1 U7.8(CPCA)
NetC54_2: C54.2 U7.10(CPCB)
NetC55_2: C55.2 U7.11(CPVOUTP)
NetC56_2: C56.2 U7.12(CPVOUTN)
NetC57_2: C57.2 U7.21(VMIDC)
NetC59_1: C59.1 CN4.2 L7.2
NetC62_1: C62.1 CN4.3 L6.2
NetC63_1: C63.1 R71.2
NetC63_2: C63.2 L6.1 U7.15(HPOUTR)
NetC64_1: C64.1 R70.2
NetC64_2: C64.2 L7.1 U7.13(HPOUTL)
NetCN4_1: CN4.1 R65.1 U7.14(HPOUTFB)
NetR47_2: R47.2 U7.25(IN1R/DMICDAT2) U7.27(IN1L/DMICDAT1)
NetR53_2: R53.2 U7.24(IN2R) U7.26(IN2L)
NetR54_2: R54.2 R55.2
NetR61_1: R61.1 U7.3(SDA)
NetR62_1: R62.1 U7.2(SCLK)
NetR63_2: R63.2 R64.1 U9.2(LR)

Not connected (* = marked no-connect by the designer): U7 16(LINEOUTL)* 17(LINEOUTFB)* 18(LINEOUTR)* 20(MICBIAS)* 31(ADCDAT)*

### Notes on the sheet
- I2S3_MCK
- I2S3_SCK
- (near R43) Audio_RST
- I2S3_WS
- I2S3_SD
- Not Fitted
- Audio_SDA
- Audio_SCL
- (near U7) I2C address Read 0x35 / Write 0x34
- Audio_DAC_OUT
- CLK_IN
- PDM_OUT
- (near R49) Not Fitted

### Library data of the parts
C40 C41 C48 C50 C53 C63 C64 = CC0402KRX7R7BB104: Capacitor, MLCC, 100nF, 16V, X7R, +/-10%, 0402, T=0.5mm
C42 C43 C45-C47 C57 = CC0603KRX5R7BB475: Capacitor, MLCC, 4.7uF, 16V, X5R, +/-10%, 0603, T=0.8mm
C44 C51 = CAP: as C28 on sheet STM32Fx
C52 = CAP: Capacitor; Manuf_Part_1: CC0603KRX7R9BB103; Manuf_1: YAGEO
C54-C56 = CC0603KRX5R6BB225: Capacitor, MLCC, 2.2uF, 10V, X5R, +/- 10%, 0603, T=0.8mm
C58 = CAP: Capacitor; Manuf_Part_1: CC0603KRX5R5BB106; Manuf_1: YAGEO
C59 C62 = CC0402JRNPO9BN471: Capacitor, MLCC, 470pF, 50V, C0G/NP0, +/-5%, 0402, T=0.5mm
C60 = CAP: Capacitor; Manuf_Part_1: CC0402KRX7R7BB104; Manuf_1: YAGEO
CN4 = ST-225-02_: Connector Jack 35mm; Manuf_1: XIEJIA Electronics
L2-L7 = BLM15AX100SN1D: Ferrite bead, 10R @100MHz, 1.74A, 0.015R, 0402
R43 = res1: as R6 on sheet ST_LINK_V2
R44 R52 = res1: as R7 on sheet ST_LINK_V2
R47 R53 = res1: as R69 on sheet ST_LINK_V2
R48 R55 R65 = res1: as R10 on sheet ST_LINK_V2
R49 = res1: Resistor; Manuf_Part_1: RC0603JR-070RL; Manuf_1: YAGEO; Fitted: NO
R54 = res1: Resistor; Manuf_Part_1: RC0603FR-071K2L; Manuf_1: YAGEO
R61 R62 = RC0402JR-070RL: Resistor, 0R, 0402, +/-5%, 1/16W
R63 = res1: Resistor; Manuf_part_1: RC0402JR-070RL; Manuf_1: YAGEO
R64 = res1: Resistor; Fitted: NO
R70 R71 = RC0603FR-0720RL: Resistor, 20R, 0603, +/-1%, 1/10W
SB22 = SB_ON: Resistor, 0R, SB0603, 5%, 0.1W
U7 = IC_WM8904CGEFL/RV
U9 = IC_CMM-4030DT-261075-TR: MEMS Microphone, Top port, -26 ±1 dB, 2V6

## Sheet IO_Peripherals.SchDoc: Peripherals
size A4; DocumentNumber: 4; Revision: D.1(PCB.SCH); SheetNumber: 4; SheetTotal: 7
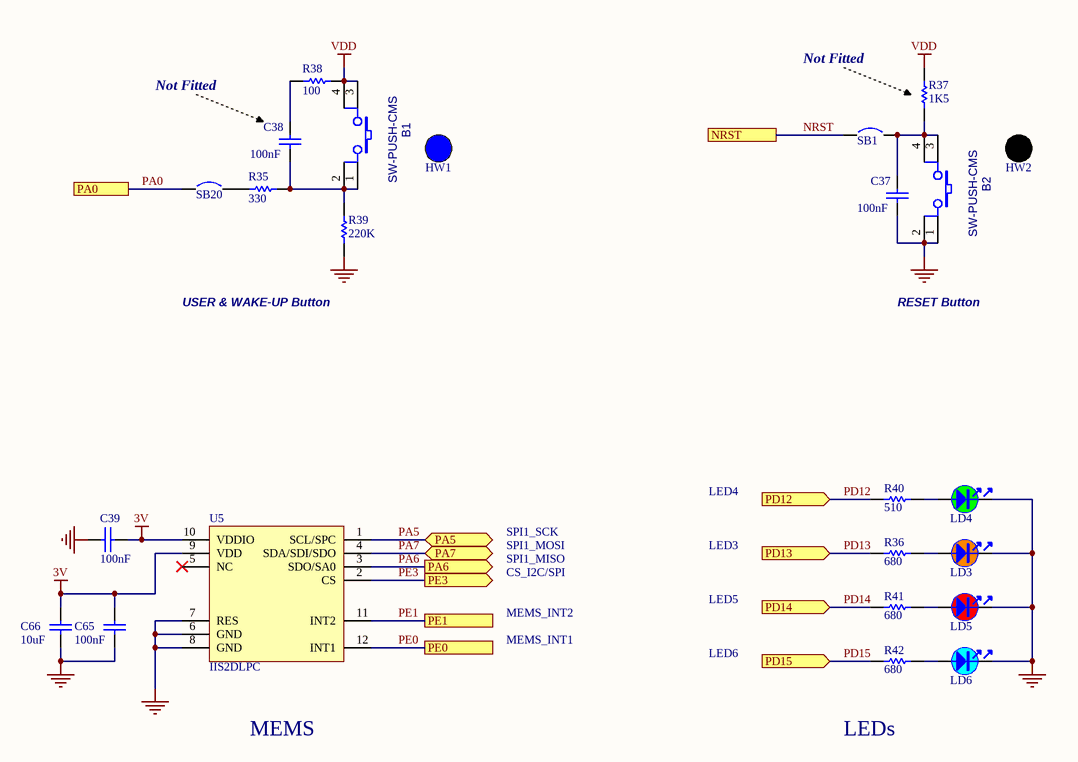
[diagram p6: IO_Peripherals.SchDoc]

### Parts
B1  SW-PUSH-CMS  [SW4SMD]
B2  SW-PUSH-CMS  [SW4SMD]
C37  100nF  [0402C]
C38  100nF  [0402C]
C39  100nF  [0402C]
C65  100nF  [C0402]
C66  10uF  [C0603]
HW1  BUTTON_HAT_BLUE  (value not drawn)  (mechanical)
HW2  BUTTON_HAT_BLACK  (value not drawn)  (mechanical)
LD3  LED_orange  [LED_0603_ORANGE_H0P4]  (value not drawn)
LD4  LED_green  [LED_0603_GREEN]  (value not drawn)
LD5  LED_red  [LED_0603_RED]  (value not drawn)
LD6  LED_blue  [LED_0603_SMD-B_BLUE_H0P4]  (value not drawn)
R35  330  [0603R]
R36  680  [0603R]
R37  1K5  [0402R]
R38  100  [0402R]
R39  220K  [0603R]
R40  510  [0603R]
R41  680  [0603R]
R42  680  [0603R]
SB1  Circuit Breaker  [JUMPER]  (value not drawn)
SB20  Circuit Breaker  [JUMPER]  (value not drawn)
U5  IIS2DLPC  [ICC_LGA12_2X2_P050_H0P7]

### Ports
NRST, PA0, PA5 (bidir), PA6 (out), PA7 (bidir), PD12 (in), PD13 (in), PD14 (in), PD15 (in), PE0, PE1, PE3 (out)

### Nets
3V: C39.2 C65.2 C66.2 U5.9(VDD) U5.10(VDDIO)
GND: B2.1 B2.2 C37.1 C39.1 C65.1 C66.1 LD3.2 LD4.2 LD5.2 LD6.2 R39.1 U5.6(GND) U5.7(RES) U5.8(GND)
VDD: B1.3 B1.4 R37.2 R38.2
NRST: SB1.1 ; port NRST
PA0: SB20.1 ; port PA0
PA5: U5.1(SCL/SPC) ; port PA5
PA6: U5.3(SDO/SA0) ; port PA6
PA7: U5.4(SDA/SDI/SDO) ; port PA7
PD12: R40.2 ; port PD12
PD13: R36.2 ; port PD13
PD14: R41.2 ; port PD14
PD15: R42.2 ; port PD15
PE0: U5.12(INT1) ; port PE0
PE1: U5.11(INT2) ; port PE1
PE3: U5.2(CS) ; port PE3
NetB1_1: B1.1 B1.2 C38.1 R35.2 R39.2
NetB2_3: B2.3 B2.4 C37.2 R37.1 SB1.2
NetC38_2: C38.2 R38.1
NetLD3_1: LD3.1 R36.1
NetLD4_1: LD4.1 R40.1
NetLD5_1: LD5.1 R41.1
NetLD6_1: LD6.1 R42.1
NetR35_1: R35.1 SB20.2

Not connected (* = marked no-connect by the designer): U5 5(NC)*

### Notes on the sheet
- Not Fitted
- USER & WAKE-UP Button
- RESET Button
- LED4
- SPI1_MOSI
- SPI1_SCK
- SPI1_MISO
- CS_I2C/SPI
- LED3
- MEMS_INT1
- MEMS_INT2
- LED5
- LED6
- MEMS
- LEDs

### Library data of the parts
B1 = SW-PUSH-CMS_NEW: Non-Open Push-Button 0.1A 24V; Manuf_1: CHAU-HUA; Manuf_Part_1: CTSM-644B-V-T/R; cap_dec: ---
B2 = SW-PUSH-CMS_NEW: Non-Open Push-Button 0.1A 24V; Manuf_1: CHAU-HUA; Manuf_Part_1: CTSM-644N-V-T/R; cap_dec: ---
C37 C39 = CAP: as C60 on sheet Audio
C38 = CAP: Capacitor; Fitted: NO
C65 = CC0402KRX7R7BB104: as C40 on sheet Audio
C66 = CC0603KRX5R5BB106: Capacitor, MLCC, 10uF, 6V3, X5R, +/-10%, 0603, T=0.8mm
HW1 = BUTTON_HAT_BLUE: switch hat,blue; Manuf_Part_1: KTSC-62B; Manuf_1: CHAU-HUA
HW2 = BUTTON_HAT_BLACK: switch hat,black; Manuf_1: CHAU-HUA; Manuf_Part_1: KTSC-62K
R35 = res1: as R66 on sheet USB_OTG_FS
R36 R41 R42 = Res1: Resistor; Manuf_Part_1: RC0603FR-07680RL; Manuf_1: YAGEO
R37 = res1: Resistor; Manuf_Part_1: RC0402FR-071K5L; Manuf_1: YAGEO; Fitted: NO
R38 = res1: as R69 on sheet ST_LINK_V2
R39 = res1: Resistor; Manuf_Part_1: RC0603FR-07220KL; Manuf_1: YAGEO
R40 = Res1: as R30 on sheet STM32Fx
SB1 SB20 = Circuit Breaker: Solder: YES
U5 = IC_IIS2DLPC

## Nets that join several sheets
1V8: ST_LINK_V2 (C17.1 C18.2 U3.5), Audio (L2.1 L3.1 L4.1)
3V: Top (P2.5 P2.6), ST_LINK_V2 (22 pins), USB_OTG_FS (R45.1 R51.1 R66.2 R67.2), Audio (6 pins), IO_Peripherals (5 pins)
5V: Top (P2.3 P2.4), ST_LINK_V2 (5 pins), USB_OTG_FS (U6.5)
GND: Top (10 pins), ST_LINK_V2 (41 pins), STM32Fx (26 pins), USB_OTG_FS (10 pins), Audio (30 pins), IO_Peripherals (14 pins)
VDD: Top (P1.3 P1.4 P2.22), ST_LINK_V2 (JP1.2 SB17.2), STM32Fx (21 pins), IO_Peripherals (B1.3 B1.4 R37.2 R38.2)
MCO: ST_LINK_V2 (C61.1 R68.2), STM32Fx (R25.1 SB13.1 U4.12)
NRST: ST_LINK_V2 (SB11.2), STM32Fx (U4.14), IO_Peripherals (SB1.1)
PA0: STM32Fx (U4.23), IO_Peripherals (SB20.1)
PA4: STM32Fx (U4.29), Audio (R48.2 U7.30)
PA5: STM32Fx (U4.30), IO_Peripherals (U5.1)
PA6: STM32Fx (U4.31), IO_Peripherals (U5.3)
PA7: STM32Fx (U4.32), IO_Peripherals (U5.4)
PA9: STM32Fx (U4.68), USB_OTG_FS (5 pins)
PA10: STM32Fx (U4.69), USB_OTG_FS (R59.2)
PA11: STM32Fx (U4.70), USB_OTG_FS (R58.1 U8.5)
PA12: STM32Fx (U4.71), USB_OTG_FS (R60.1 U8.6)
PA13: ST_LINK_V2 (SB9.1), STM32Fx (U4.72)
PA14: ST_LINK_V2 (SB5.1), STM32Fx (U4.76)
PB3: ST_LINK_V2 (SB12.2), STM32Fx (U4.89)
PB6: STM32Fx (R33.2 U4.92), Audio (R62.2)
PB9: STM32Fx (R29.2 U4.96), Audio (R61.2)
PB10: STM32Fx (U4.47), Audio (U9.3)
PC0: STM32Fx (U4.15), USB_OTG_FS (R46.2)
PC3: STM32Fx (U4.18), Audio (R55.1 U9.4)
PC4: STM32Fx (U4.33), Audio (R49.1)
PC7: STM32Fx (U4.64), Audio (U7.28)
PC10: STM32Fx (U4.78), Audio (U7.29)
PC12: STM32Fx (U4.80), Audio (U7.32)
PD4: STM32Fx (U4.85), Audio (R43.1 U7.1)
PD5: STM32Fx (U4.86), USB_OTG_FS (R50.1)
PD12: STM32Fx (U4.59), IO_Peripherals (R40.2)
PD13: STM32Fx (U4.60), IO_Peripherals (R36.2)
PD14: STM32Fx (U4.61), IO_Peripherals (R41.2)
PD15: STM32Fx (U4.62), IO_Peripherals (R42.2)
PE0: STM32Fx (U4.97), IO_Peripherals (U5.12)
PE1: STM32Fx (U4.98), IO_Peripherals (U5.11)
PE3: STM32Fx (U4.2), IO_Peripherals (U5.2)

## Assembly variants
F407VGT6: not fitted C16 C27 C61 R2 R21 R22 R27 R43 R49 R57 R58 R60 R64 SB2 SB4 SB6 SB8 SB10 SB13 SB14 SB17 SB19 X3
